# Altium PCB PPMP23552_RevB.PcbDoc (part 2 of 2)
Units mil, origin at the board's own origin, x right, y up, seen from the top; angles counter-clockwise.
Board outline 4950 x 3450 mil, 4 copper layers (Top Layer 1, Layer 2, Layer 3, Bottom Layer), stack 75.824 mil thick; 113 components, 58 nets, 311 pads, 148 vias.
Unrouted connection lines stored in the file: 10.
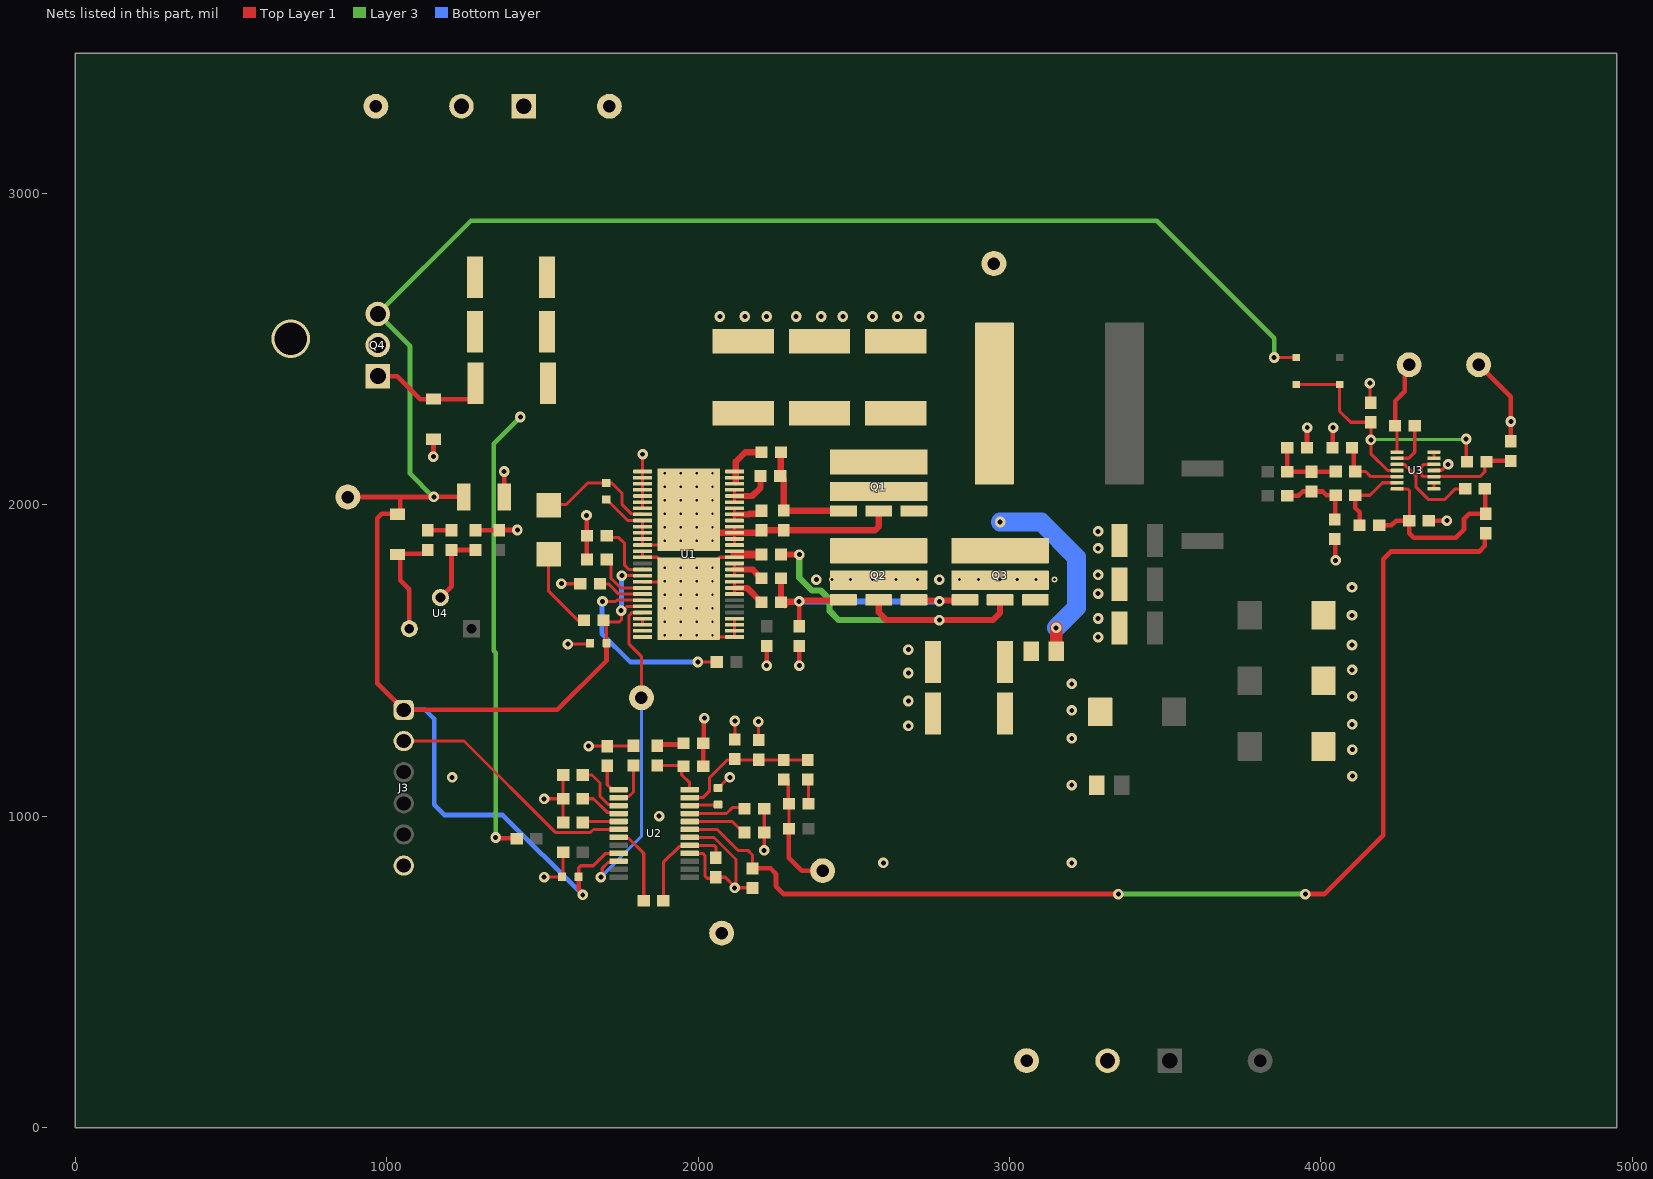
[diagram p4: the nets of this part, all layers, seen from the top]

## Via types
v1: diameter 34, hole 16, Top Layer 1 to Bottom Layer, 89 vias
v2: diameter 19.68, hole 7.87, Top Layer 1 to Bottom Layer, tented both sides, 48 vias
v3: diameter 20, hole 10, Top Layer 1 to Bottom Layer, 11 vias

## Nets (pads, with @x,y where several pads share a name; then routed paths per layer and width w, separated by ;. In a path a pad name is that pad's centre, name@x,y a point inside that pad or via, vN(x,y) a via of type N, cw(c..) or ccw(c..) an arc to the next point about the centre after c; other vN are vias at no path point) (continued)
GND: C3.1 C4.2 C5.2 C6.2 C7.2 C8.1 C10.2 C11.1 C12.1 C13.1 C14.1 C15.1 C16.2 C17.2 C18.2 C19.1 C20.2 C21.1 C22.2 C24.1 C25.1 C26.1 C27.2 C29.2 C30.2 C31.2 D5.2 H1.1 J1.2 J2.2 J3.6 Q2.4 Q3.4 R8.2 R11.1 R12.1 R13.1 R16.1 R18.1 R19.2 R20.2 R21.1 R22.1 R23.2 R25.1 R27.2 R28.2 R29.1 R30.2 R32.1 R46.1 R47.1 TP3.1 TP7.1 TP8.1 TP11.1 U1.1 U1.2 U1.3 U1.4 U1.5 U1.6 U1.7 U1.14 U1.15 U1.19 U1.25 U1.26 U1.27 U1.28 U1.29 U1.30 U1.31 U1.32 U1.42 U1.43 U1.58 U2.16 U2.18 U3.11 | length 3843.7
  Top Layer 1 w10: C30.2@1361.57,1918.22 C30.2@1362.68,1919.33 ; v1(1505.57,804.31) 1566.59,804.31 R18.1@1566.59,884.48 ; v1(1505.57,1056.05) R19.2@1566.59,1056.05 ; v1(1560.92,1746.72) R13.1@1620.17,1746.72 ; C20.2@1566.59,979.61 R23.2@1566.59,1132.48 ; v1(1582.03,1552.78) C3.1@1642.89,1552.78 ; R13.1@1618.69,1746.72 R13.1@1624.58,1752.61 ; v1(1648.44,1225) R21.1@1713.31,1225 ; R20.2@1786.17,1225 1716.05,1225 1791.57,1225 R20.2@1792.56,1225.99 ; U1.26@1821.85,1614.97 U1.25@1821.85,1634.66 ; U1.19@1821.85,1752.77 1890.75,1752.77 v2(1892.72,1754.74) ; U1.14@1821.85,1851.19 U1.15@1821.85,1831.51 1869.1,1831.51 U1.58@1969.49,1731.12 ; U1.7@1821.85,1988.99 U1.6@1821.85,2008.68 U1.5@1821.85,2028.36 U1.4@1821.85,2048.05 U1.3@1821.85,2067.73 U1.2@1821.85,2087.42 U1.1@1821.85,2107.1 v1(1821.85,2162.45) ; U1.58@1969.49,1698.64 U1.58@1969.49,1731.12 ; U2.16@1972.92,880.68 2014.75,880.68 2021.65,873.78 2021.65,807.84 2028.55,800.94 2054.14,800.94 C10.2@2057.09,803.89 2087.44,803.89 2117.13,774.2 v1(2117.13,770.2) ; U2.18@1972.92,931.86 2050.92,931.86 2121.89,860.9 2121.89,792.2 2121.72,792.04 2121.72,774.8 v1(2117.13,770.2) ; v2(2046.26,1581.51) 2052.17,1575.6 U1.29@2117.13,1575.6 U1.30@2117.13,1595.29 U1.31@2117.13,1614.97 U1.32@2117.13,1634.66 ; C24.1@2063.88,1090.53 2064.86,1090.53 2099.04,1124.7 v1(2101.78,1124.7) ; 2117.13,1840.95 U1.42@2117.13,1831.51 2069.89,1831.51 U1.58@1969.49,1731.12 ; v1(2118.19,1305.66) 2118.19,1246.72 R11.1@2118.25,1246.66 ; R22.1@2174.88,769.44 2174.12,770.2 v1(2117.13,770.2) ; v1(2193.58,1303.69) 2193.58,1245.8 R12.1@2194.69,1244.69 ; v1(2212.33,890.37) C22.2@2212.33,947.88 R25.1@2212.33,1024.38 ; v1(4157.64,2391) 4157.64,2331.32 C25.1@4160.78,2328.18 ; U3.11@4363.11,2110.32 4364.02,2111.22 4387.97,2111.22 4406.75,2130 v1(4408.65,2130)
  Top Layer 1 w15: v1(1150,2155) D5.2@1150,2210.53 ; R46.1@1285.07,1918.22 C30.2@1361.57,1918.22 ; C30.2@1362.68,1919.33 v1(1419.63,1919.33) ; C29.2@1377.29,2025 v1(1377.29,2107.21) ; v1(1641.62,1966.15) 1642.6,1965.16 1642.6,1901.77 C4.2@1643.58,1900.78 ; C4.2@1641.96,1894.64 1642.42,1894.18 1642.42,1823.76 R16.1@1642.89,1823.3 ; C19.1@2016.5,1160.79 C11.1@2016.5,1234.85 2018.25,1236.6 2018.25,1313.25 v1(2020,1315) ; v1(2220,1483.38) C21.1@2220,1546.88 ; v1(2325,1483.38) R29.1@2325,1546.88 ; C31.2@3955.27,2183.52 3955.8,2184.05 3955.8,2247.35 v1(3956.33,2247.87) ; R47.1@4037.05,2183.52 4038.15,2184.63 4038.15,2246.77 v1(4039.25,2247.87) ; C26.1@4045.15,1890 4046.4,1888.75 4046.4,1823.26 v1(4047.66,1822.01) ; C27.2@4346.5,1949.37 v1(4405,1949.37) ; TP11.1@4506.75,2450 4610,2346.75 v1(4610,2267.62) R32.1@4610,2204.11
  Top Layer 1 w25: 2117.13,1840.95 2203.1,1840.95 R30.2@2203.58,1840.47
  other v1: 2595,850 3200,850 1875,1000 3200,1100 1210,1125 4101.02,1128.54 4101.02,1213.54 3200,1250 2675,1290 4100.81,1295 3200,1340 2675,1370 4100.81,1385 3200,1425 2675,1460 4100.81,1470 2675,1535 4100,1550 3285,1575 3285,1635 4100,1645 3285,1715 4100,1735 2380,1760 2775,1760 3285,1775 3285,1860 3285,1915 2070,2605 2150,2605 2220,2605 2315,2605 2395,2605 2465,2605 2560,2605 2640,2605 2710,2605
  other v2: 1892.72,1581.51 1943.9,1581.51 1995.08,1581.51 1892.72,1624.82 1943.9,1624.82 1995.08,1624.82 2046.26,1624.82 1892.72,1668.12 1943.9,1668.12 1995.08,1668.12 2046.26,1668.12 1892.72,1711.43 1943.9,1711.43 1995.08,1711.43 2046.26,1711.43 1943.9,1754.74 1995.08,1754.74 2046.26,1754.74 1892.72,1798.05 1943.9,1798.05 1995.08,1798.05 2046.26,1798.05
  other v3: 2430,1760 2490,1760 2560,1760 2635,1760 2705,1760 2840,1760 2900,1760 2970,1760 3025,1760 3085,1760 3145,1760
LSG: Q2.1 Q2.2 Q3.1 Q3.2 R24.2 R26.2 R29.2 | length 984.1
  Top Layer 1 w15: R24.2@2278.34,1674.33 2291.15,1687.14 ; R29.2@2325,1609.87 v1@2325,1674.33
  Top Layer 1 w20: R24.2@2266.57,1688.76 R24.2@2278.28,1688.76 ; R26.2@2266.57,1763.96 2266.57,1700.48 2272.43,1694.62 R24.2@2278.28,1688.76 ; Q2.1@2467.01,1695 2464.39,1692.38 2327.39,1692.38 2323.77,1688.76 R24.2@2278.28,1688.76 ; Q2.2@2692.99,1695 2695.49,1692.5 2772.5,1692.5 v1(2775,1690) 2777.5,1692.5 2854.51,1692.5 Q3.1@2857.01,1695
  Bottom Layer w20: v1(2324.77,1689.76) 2324.89,1689.88 2774.88,1689.88 v1(2775,1690)
NetC1_1: C1.1 D1.1 U1.8 | length 393.1
  Top Layer 1 w10: D1.1@1520.02,2001.23 1576.59,2001.23 1645.47,2070.11 C1.1@1705.39,2070.11 1723.1,2070.11 1755.13,2038.09 1755.13,2002.23 1787.15,1970.21 1820.95,1970.21 U1.8@1821.85,1969.3
NetC2_2: C2.2 U1.48 U1.49 U1.50 | length 131.3
  Top Layer 1 w10: U1.48@2117.13,1949.62 U1.49@2117.13,1969.3 U1.50@2117.13,1988.99
  Top Layer 1 w20: U1.49@2117.13,1969.3 2162.61,1969.3 2164.74,1971.43 2194.87,1971.43 2203.58,1980.13 C2.2@2203.58,1981.12
NetC4_1: C4.1 U1.17 | length 201.6
  Top Layer 1 w10: C4.1@1704.95,1894.64 1745.31,1894.64 1764.01,1875.94 1764.01,1805.94 1777.82,1792.14 U1.17@1821.85,1792.14 U1.17@1820.95,1793.05
NetC9_1: C9.1 R4.1 | length 82.4
  Top Layer 1 w10: R4.1@2354.65,1040.06 2354.65,1106.28 C9.1@2366.09,1117.72
NetC9_2: C9.2 R5.1 R11.2 R12.2 U2.23 | length 468.8
  Top Layer 1 w10: U2.23@1972.92,1059.82 2015.45,1059.82 2037.22,1081.59 2037.22,1124.27 2092.68,1179.73 2092.68,1180.71 2120.85,1180.71 2169.36,1180.71 2194.69,1180.71 2289.59,1180.71 C9.2@2366.09,1180.71
NetC10_1: C10.1 R17.2 U2.17 | length 350.4
  Top Layer 1 w10: R17.2@1888.43,728.53 1888.43,851.65 1939.2,902.41 1969.06,902.41 U2.17@1972.92,906.27 2051.24,906.27 2057.09,900.42 C10.1@2057.09,866.88
NetC11_2: C11.2 R15.2 | length 87.8
  Top Layer 1 w15: R15.2@1869.33,1225.99 1873.76,1230.42 1949.07,1230.42 C11.2@1953.5,1234.85
NetC19_2: C19.2 R15.1 U2.24 | length 165.1
  Top Layer 1 w10: R15.1@1869.33,1163 1945.45,1163 1947.66,1160.79 1947.66,1132.58 1972.92,1107.32 U2.24@1972.92,1085.41
NetC20_1: C20.1 U2.5 | length 116.4
  Top Layer 1 w10: C20.1@1629.58,979.61 1633.02,983.04 U2.5@1744.57,983.04
NetC22_1: C22.1 U2.20 | length 188
  Top Layer 1 w10: U2.20@1972.92,983.04 2110.24,983.04 2145.4,947.88 C22.1@2146.39,947.88
NetC23_1: C23.1 R27.1 R28.1
NetC24_2: C24.2 U2.22 | length 92.3
  Top Layer 1 w10: U2.22@1972.92,1034.23 1974.5,1035.8 2062.3,1035.8 C24.2@2063.88,1037.38
NetC25_2: C25.2 D2.1 D3.1 R31.1 U3.4 | length 923.1
  Top Layer 1 w10: D2.1@3920.76,2386.7 D3.1@4060.15,2386.7 4060.15,2301.06 4096.02,2265.18 C25.2@4160.78,2265.18 v1(4160.78,2208.82) 4160.78,2164.62 4215.08,2110.32 U3.4@4245,2110.32 ; v1(4466.85,2211.31) 4466.85,2141.12 R31.1@4469.35,2138.62
  Layer 3 w10: v1(4160.78,2208.82) 4162.4,2210.44 4459.38,2210.44 v1@4461,2212.07
NetC26_2: C26.2 C28.1 R38.2 R39.1 | length 244.7
  Top Layer 1 w15: R38.2@3892.28,2029.43 3928.01,2029.43 3941.46,2042.87 C28.1@3970,2042.87 4005.9,2042.87 4018.13,2030.65 R39.1@4047.66,2030.65 4046.4,2029.4 4046.4,1954.24 C26.2@4045.15,1952.99
NetC27_1: C27.1 R36.2 R37.1 R40.2 U3.7 | length 665.9
  Top Layer 1 w10: U3.7@4245,2051.26 4278.11,2051.26 4285,2044.37 4285,1950.87 C27.1@4283.5,1949.37
  Top Layer 1 w15: R40.2@4187.5,1934.38 4226.78,1934.38 4241.77,1949.37 C27.1@4283.5,1949.37 4283.5,1909.37 4298.5,1894.37 4433.46,1894.37 4460,1920.91 4460,1955.39 4476.3,1971.69 R36.2@4529.45,1971.69 4527.97,1973.17 4527.97,2049.78 R37.1@4526.5,2051.26
NetC28_2: C28.2 C31.1 R43.2 R44.1 | length 233.5
  Top Layer 1 w15: C31.1@3892.28,2183.52 R43.2@3892.28,2105.87 C28.2@3970,2105.87 3970.61,2106.48 4047.05,2106.48 R44.1@4047.66,2107.09
NetD1_2: D1.2 R1.2 | length 282.7
  Top Layer 1 w10: D1.2@1520.02,1843.75 1520.02,1722.56 1613.36,1629.22 R1.2@1642.89,1629.22
NetD4_2: D4.2 R41.2 U4.3 | length 354.3
  Top Layer 1 w10: R41.2@1118.91,1842.65 R41.2@1131.48,1855.22
  Top Layer 1 w15: U4.3@1072.47,1602.15 1072.47,1728.59 1043.42,1757.64 1043.42,1842.46 R41.2@1127.56,1842.46
NetD5_1: D5.1 Q4.1 R33.2 | length 384.1
  Top Layer 1 w15: Q4.1@971.41,2413.19 1033.77,2413.19 1107.5,2339.47 D5.1@1150,2339.47 1266.91,2339.47 1285,2357.56 R33.2@1285,2390
NetQ1_1: Q1.1 Q1.2 R3.2 R6.2 R9.2 | length 390.8
  Top Layer 1 w20: R6.2@2269.52,2171.93 R6.2@2266.57,2168.98 2265.09,2167.5 2265.09,2094.02 R3.2@2263.61,2092.54 2264.6,2092.54 2273.3,2083.84 2273.3,2082.86 2275,2081.16 R9.2@2275,1981.5 2275.75,1980.75 2466.26,1980.75 Q1.1@2467.01,1980
NetQ4_2: Q4.2 R34.1 R35.1
NetR2_1: R2.1 R4.2 R5.2 TP2.1 | length 377.4
  Top Layer 1 w10: R5.2@2289.59,1117.72 2289.59,1042.13 R4.2@2291.66,1040.06 R2.1@2291.66,960.05
  Top Layer 1 w15: R2.1@2291.66,960.05 2291.66,866.88 2333.54,825 TP2.1@2400,825
NetR3_1: R3.1 U1.51 U1.52 U1.53 | length 171.2
  Top Layer 1 w10: U1.51@2117.13,2008.68 U1.52@2117.13,2028.36 U1.53@2117.13,2048.05
  Top Layer 1 w20: U1.52@2117.13,2028.36 2173.65,2028.36 2200.62,2055.34 R3.1@2200.62,2092.54
NetR6_1: R6.1 U1.54 U1.55 U1.56 | length 161.3
  Top Layer 1 w20: U1.54@2121.23,2072.4 2121.23,2138.82 2151.38,2168.98 R6.1@2203.58,2168.98
NetR7_1: R7.1 U1.22 | length 641.7
  Top Layer 1 w10: v1(1693.08,1689.76) 1735.01,1689.76 1739.44,1694.19 1821.38,1694.19 U1.22@1821.85,1693.71 ; v1(1999.01,1495.3) R7.1@2060.04,1495.3
  Bottom Layer w10: v1@1691.2,1687.87 v1(1693.08,1689.76)
  Bottom Layer w15: v1@1691.2,1687.87 1691.2,1586.16 1782.06,1495.3 v1(1999.01,1495.3)
NetR13_2: R13.2 U1.21 | length 150.8
  Top Layer 1 w10: R13.2@1684.92,1746.93 1686.64,1745.21 1713.75,1745.21 1745.56,1713.4 U1.21@1821.85,1713.4
NetR16_2: R16.2 U1.20 | length 176.4
  Top Layer 1 w10: R16.2@1719.37,1825.57 1720.56,1824.37 1720.56,1763.67 1751.15,1733.08 U1.20@1821.85,1733.08
NetR17_1: R17.1 U2.7 | length 254.3
  Top Layer 1 w10: U2.7@1744.57,931.86 1748.43,928.01 1778.29,928.01 1825.44,880.86 R17.1@1825.44,728.53
NetR19_1: R19.1 U2.4 | length 134.6
  Top Layer 1 w10: R19.1@1629.58,1056.05 1664.27,1056.05 1707.82,1012.49 1740.71,1012.49 U2.4@1744.57,1008.64
NetR20_1: R20.1 U2.2 | length 140.6
  Top Layer 1 w10: U2.2@1744.57,1059.82 1748.43,1063.67 1778.29,1063.67 1792.56,1077.94 R20.1@1792.56,1163
NetR21_2: R21.2 U2.1 | length 103.8
  Top Layer 1 w10: R21.2@1708.14,1162.01 1708.14,1101.17 1723.9,1085.41 U2.1@1744.57,1085.41
NetR22_2: R22.2 R36.1 U2.19 | length 3712.2
  Top Layer 1 w10: U2.19@1972.92,957.45 2061.21,957.45 2128.29,890.37 2159.84,890.37 2174.88,875.33 R22.2@2174.88,832.43
  Top Layer 1 w15: R22.2@2174.88,832.43 2232.57,832.43 2250,815 2250,775 2275,750 v1(3350,750) ; v1(3950,750) 4011.23,750 4200,938.77 4200,1825 4225,1850 4508.49,1850 4526.5,1868.01 4526.5,1905.75 R36.1@4529.45,1908.7
  Layer 3 w15: v1(3350,750) v1(3950,750)
NetR23_1: R23.1 U2.3 | length 180.7
  Top Layer 1 w10: R23.1@1629.58,1132.48 1659.11,1132.48 1684.98,1106.61 1684.98,1063.96 1710.85,1038.08 1740.71,1038.08 U2.3@1744.57,1034.23
NetR24_1: R24.1 U1.36 U1.37 U1.38 | length 144.7
  Top Layer 1 w10: U1.36@2117.13,1713.4 U1.37@2117.13,1733.08 U1.38@2117.13,1752.77
  Top Layer 1 w20: U1.37@2117.13,1733.08 2157.03,1733.08 2202.59,1687.53 R24.1@2203.58,1687.53
NetR25_2: R25.2 U2.21 | length 185.5
  Top Layer 1 w10: U2.21@1972.92,1008.64 2091.37,1008.64 2110.24,1027.5 2146.22,1027.5 R25.2@2149.34,1024.38
NetR26_1: R26.1 U1.39 U1.40 U1.41 | length 150.1
  Top Layer 1 w10: U1.39@2117.13,1772.45 U1.40@2117.13,1792.14 U1.41@2117.13,1811.82 ; R26.1@2195.08,1772.45 R26.1@2203.57,1763.96
  Top Layer 1 w20: U1.40@2117.13,1792.14 2175.4,1792.14 2187.12,1780.42 2187.12,1779.44 2194.59,1771.96 2202.59,1763.96 R26.1@2203.57,1763.96
NetR31_2: R31.2 R32.2 U3.10 U3.12 | length 389.7
  Top Layer 1 w10: U3.12@4363.11,2130 4331.02,2130 4322.97,2121.95 4322.97,2096.49 4328.83,2090.63 U3.10@4363.11,2090.63 4511.26,2090.63 4526.5,2105.87 R31.2@4526.5,2139.37
  Top Layer 1 w15: R31.2@4526.5,2139.37 4528.25,2141.12 4598.25,2141.12 R32.2@4600,2142.87
NetR37_2: R37.2 U3.3 | length 300.7
  Top Layer 1 w10: U3.3@4245,2130 4245.91,2129.09 4269.86,2129.09 4305.1,2093.86 4305.1,2058.08 4346.5,2016.68 4397.31,2016.68 4431.89,2051.26 R37.2@4463.5,2051.26
NetR39_2: R39.2 R40.1 U3.6 | length 254
  Top Layer 1 w10: R39.2@4110.65,2030.65 4157.64,2030.65 4197.93,2070.94 U3.6@4245,2070.94
  Top Layer 1 w15: R39.2@4110.65,2030.65 4110.65,1989.82 4124.51,1975.97 R40.1@4124.51,1934.38 ; R40.1@4127.95,1934.38 R40.1@4128.93,1934.38
NetR41_1: R41.1 R42.1 | length 76.4
  Top Layer 1 w15: R41.1@1131.48,1918.22 R42.1@1207.92,1918.22
NetR42_2: R42.2 R46.2 U4.2 | length 245.6
  Top Layer 1 w15: U4.2@1172.47,1702.15 1207.92,1737.6 R42.2@1207.92,1855.22 1283.35,1855.22 R46.2@1285.07,1853.5
NetR44_2: R44.2 R47.2 U3.5 | length 222
  Top Layer 1 w10: R44.2@4110.65,2107.09 4144,2107.09 4160.45,2090.63 U3.5@4245,2090.63
  Top Layer 1 w15: R47.2@4100.04,2183.52 4105.34,2178.22 4105.34,2112.39 R44.2@4110.65,2107.09
NetR45_1: R45.1 TP10.1 U3.1 | length 296.3
  Top Layer 1 w10: R45.1@4238.5,2254.37 4245,2247.87 U3.1@4245,2169.37
  Top Layer 1 w15: R45.1@4238.5,2254.37 4238.5,2333.51 4269.23,2364.24 4269.23,2449.37 TP10.1@4269.86,2450
NetR45_2: R45.2 U3.2 | length 149.6
  Top Layer 1 w10: U3.2@4245,2149.69 4281.81,2149.69 4301.5,2169.37 R45.2@4301.5,2254.37
NetU3_8: U3.8 U3.9 | length 19.7
  Top Layer 1 w10: U3.8@4363.11,2051.26 U3.9@4363.11,2070.94
NetU3_13: U3.13 U3.14 | length 19.7
  Top Layer 1 w10: U3.13@4363.11,2149.69 U3.14@4363.11,2169.37
PWM: TP4.1 U1.24 U2.10 | length 1050.1
  Top Layer 1 w10: v1(1687.51,804.31) 1692.1,808.9 1692.1,832.48 1710.85,851.23 1740.71,851.23 U2.10@1744.57,855.09 ; TP4.1@1817.92,1380.4 1817.92,1513.3 1778.47,1552.74 1778.47,1644.76 1787.15,1653.44 1820.95,1653.44 U1.24@1821.85,1654.34
  Bottom Layer w10: v1(1687.51,804.31) 1817.92,934.72 TP4.1@1817.92,1380.4
SS: Q2.5 Q3.5 R30.1 | length 1152.5
  Top Layer 1 w20: R30.1@2266.57,1840.47 2266.8,1840.23 2324.77,1840.23 v1(2325,1840) ; Q2.5@2580,1695 2580,1655.08 2605.08,1630 v1(2775,1630) 2946.68,1630 2970,1653.32 Q3.5@2970,1695
  Layer 3 w20: v1(2325,1840) 2325,1765.68 2365.55,1725.13 2393.04,1725.13 2422.11,1696.06 2422.11,1659.07 2451.17,1630 v1(2775,1630)
SW: C1.2 C2.1 C23.2 L1.1 Q1.4 Q1.5 Q2.3 Q3.3 R9.1 TP5.1 U1.9 U1.10 U1.11 U1.12 U1.13 U1.44 U1.45 U1.46 U1.47 U1.57 | length 1885.6
  Top Layer 1 w10: C1.2@1705.39,2016.96 1706.37,2016.96 1773.71,1949.62 U1.9@1821.85,1949.62 U1.10@1821.85,1929.93 U1.11@1821.85,1910.25 U1.12@1821.85,1890.56 U1.13@1821.85,1870.88 1874.1,1870.88 1969.49,1966.27 U1.57@1969.49,1984.07 ; U1.57@2001.44,1934.32 U1.57@2048.69,1887.08 ; v2(2046.26,1884.66) U1.57@2052.17,1890.56 ; U1.44@2117.13,1870.88 U1.45@2117.13,1890.56 U1.46@2117.13,1910.25 U1.47@2117.13,1929.93
  Top Layer 1 w20: U1.57@1969.49,1984.07 2043.31,1910.25 U1.46@2117.13,1910.25 2195.7,1910.25 C2.1@2203.58,1918.12 2203.77,1918.31 2274.81,1918.31 R9.1@2275,1918.5 2568.28,1918.5 2580,1930.22 Q1.5@2580,1980
  Top Layer 1 w40: Q3.3@2970,1852.5 Q3.3@2972.5,1855 ; C23.2@3150,1530 v1(3150,1605)
  Bottom Layer w60: v1(2970,1945) 3101.85,1945 3215,1831.85 3215,1670 v1(3150,1605)
  other v2: 1892.72,1884.66 1943.9,1884.66 1995.08,1884.66 1892.72,1927.97 1943.9,1927.97 1995.08,1927.97 2046.26,1927.97 1892.72,1971.27 1943.9,1971.27 1995.08,1971.27 2046.26,1971.27 1892.72,2014.58 1943.9,2014.58 1995.08,2014.58 2046.26,2014.58 1892.72,2057.89 1943.9,2057.89 1995.08,2057.89 2046.26,2057.89 1892.72,2101.19 1943.9,2101.19 1995.08,2101.19 2046.26,2101.19
SYNC: J3.2 U2.6 | length 815.2
  Top Layer 1 w10: J3.2@1054.75,1241.4 1248.21,1241.4 1541.57,948.03 1654.6,948.03 1664.02,957.45 U2.6@1744.57,957.45
Vbias: C3.2 C8.2 C29.1 D2.2 D4.1 J3.1 Q4.3 R1.1 TP9.1 U1.18 U1.23 U2.9 | length 7524.5
  Top Layer 1 w10: C8.2@1616.57,805 1616.57,834.73 1622.63,840.78 1663.62,840.78 1703.52,880.68 U2.9@1744.57,880.68 ; C3.2@1705.88,1552.78 1705.88,1629.22 1710.87,1624.23 1747.65,1624.23 1753.51,1630.08 1753.51,1659.65 v1(1752.92,1660.24) ; v1@1753.51,1661.22 1753.6,1661.31 1760.09,1661.31 1772.82,1674.03 U1.23@1821.85,1674.03 ; v1(1755.13,1772.45) U1.18@1821.85,1772.45 ; v1(3850,2473.31) D2.2@3920.76,2473.31
  Top Layer 1 w15: TP9.1@875,2025 1043.42,2025 ; D4.1@1034.75,1971.4 984.75,1971.4 969.75,1956.4 969.75,1426.4 J3.1@1054.75,1341.4 1547.98,1341.4 1705.88,1499.29 C3.2@1705.88,1552.78 ; D4.1@1034.75,1978.53 1043.42,1969.86 1043.42,2025 ; v1@1150,2025 1043.42,2025 ; v1(1151.39,2025.77) 1246.6,2025.77 C29.1@1247.37,2025 ; C8.2@1616.57,805 1616.57,765.38 1629.58,752.37 v1(1629.58,747.23)
  Layer 3 w15: v1@1150,2025 1075,2100 1075,2509.6 Q4.3@971.41,2613.19 1270.71,2912.5 3472.5,2912.5 3850,2535 v1(3850,2473.31)
  Bottom Layer w10: v1(1752.92,1660.24) v1@1754.02,1661.34 ; v1@1754.02,1771.35 v1(1755.13,1772.45) v1@1759.72,1767.86
  Bottom Layer w15: J3.1@1054.75,1341.4 1123,1341.4 1152.19,1312.21 1152.19,1037.34 1185.78,1003.75 1373.06,1003.75 v1(1629.58,747.23) ; v1@1754.02,1661.34 v1@1754.02,1771.35
Vin: C5.1 C6.1 C7.1 J1.1 Q1.3 R10.2 R33.1 R34.2 R35.2 TP1.1 | length 1457.3
  Top Layer 1 w15: v1(1350,931.51) 1351.75,929.76 1415.56,929.76 R10.2@1417.31,928.01
  Layer 3 w15: v1(1350,931.51) 1350,1525.01 1343.53,1531.48 1343.53,2196.5 v1(1429,2281.98)
pads on no net: H2.0 H3.0 H4.0 H5.0 J3.3 J3.4 U1.16 U2.11 U2.12 U2.13 U2.14 U2.15

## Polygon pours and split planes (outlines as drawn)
GND on Top Layer 1 "TOP_LAYER_1_GND_P026" (solid, remove dead copper, pour order 26): 50,3400 50,50 4900,50 4900,3400
NetC23_1 on Top Layer 1 "TOP_LAYER_1_NETC23_1_P025" (solid, remove dead copper, pour order 25): 3095,1570 2925,1570 2925,1250 3095,1250
NetQ4_2 on Top Layer 1 "TOP_LAYER_1_NETQ4_2_P024" (solid, remove dead copper, pour order 24): 1350,2475 900,2475 900,2550 1150,2550 1150,2850 1350,2850
NetD5_1 on Top Layer 1 "TOP_LAYER_1_NETD5_1_P022" (solid, remove dead copper, pour order 22): 900,2300 1350,2300 1350,2450 900,2450
CS- on Top Layer 1 "TOP_LAYER_1_CS-_P021" (solid, remove dead copper, pour order 21): 3865,1950 3865,50 3435,50 3435,1950
CS+ on Top Layer 1 "TOP_LAYER_1_CS+_P020" (solid, remove dead copper, pour order 20): 3200,2000 3465,2000 3700,2000 3700,2850 3200,2850
SW on Top Layer 1 "TOP_LAYER_1_SW_P019" (solid, remove dead copper, pour order 19): 2400,2070 2400,2015 2540,2015 2540,1930 2400,1930 2400,1815 3135,1815 3135,2850 2825,2850 2825,1930 2620,1930 2620,2015 2750,2015 2750,2070
Vin on Top Layer 1 "TOP_LAYER_1_VIN_P017" (solid, remove dead copper, pour order 17): 1400,3400 1400,2850 1400,2250 2400,2250 2400,2100 2800,2100 2800,2425 1950,2425 1950,3400
GND on Bottom Layer "BOTTOM_LAYER_GND_P023" (solid, pour order 23): 50,3400 50,50 4900,50 4900,3400
CS- on Bottom Layer "BOTTOM_LAYER_CS-_P018" (solid, remove dead copper, pour order 18): 3865,1950 3865,50 3435,50 3435,1950
SW on Bottom Layer "BOTTOM_LAYER_SW_P011" (solid, remove dead copper, pour order 11): 2072.1,2150.72 2072.1,1852.1 2070,1850 1870,1850 1870,2150
GND on Layer 2 "LAYER_2_GND_P014" (solid, pour order 14): 50,3400 50,50 4900,50 4900,3400
GND on Layer 3 "LAYER_3_GND_P015" (solid, pour order 15): 50,3400 50,50 4900,50 4900,3400

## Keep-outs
Keep-Out Layer:
  text ".Layer_Name" at 577,-858.49 h60

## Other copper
Top Layer 1:
  rectangle net GND: 3070,1730 3200,1785
  rectangle net GND: 2690,1730 2860,1785
  rectangle net GND: 2360,1730 2455,1785
  rectangle net SW: 2725,2015 2895,2070
  text ".Layer_Name" at 577,-858.49 h60
Bottom Layer:
  text ".Layer_Name" at 577,-858.49 h60

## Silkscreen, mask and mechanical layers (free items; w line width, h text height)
Top Overlay:
  text "VIN" at 1858,3253 h50
  text "GND" at 683,3248 h50
  text "'.PRJ_Number'.PCB_Rev" at 1175,262.76 h108.27
  text "GND" at 2955.92,48 h50
  text "VOUT" at 3777.5,48 h50
  text ".Layer_Name" at 577,-858.49 h60
Bottom Overlay:
  text ".Layer_Name" at 577,-858.49 h60
Top Paste:
  text ".Layer_Name" at 577,-858.49 h60
Bottom Paste:
  text ".Layer_Name" at 577,-858.49 h60
Top Solder:
  text ".Layer_Name" at 577,-858.49 h60
  text ".Layer_Name" at 577,-858.49 h60
Bottom Solder:
  text ".Layer_Name" at 577,-858.49 h60
Drill Guide:
  text ".Layer_Name" at 577,-858.49 h60
M1 Board Outline:
  the board outline again, w10
  text ".Layer_Name" at 577,-858.49 h60
M2 Board Dimensions:
  rectangle: 0,-275 125,-150
  rectangle: 125,-400 500,-275
  lines w7: 0,-275 1000,-275 ; 125,-400 125,-150 ; 250,-400 250,-150 ; 500,-400 500,-150 ; 750,-400 750,-150 ; 0,-400 1000,-400 1000,-150 0,-150 0,-400
  text ".Layer_Name" at 577,-858.49 h60
M3 3D STEP Top:
  text ".Layer_Name" at 577,-858.49 h60
M4 3D STEP Bottom:
  text ".Layer_Name" at 577,-858.49 h60
M5 Assembly Top:
  lines w10: -292,-930.17 6308,-930.17 ; -292,-726.83 6310,-726.83 ; -292,-523.5 -292,-1133.5 3713,-1133.5 6310,-1133.5 6310,-523.5 -291.5,-523.5 -291.5,-1133.5 1284,-1133.5 ; 2173,-1133.5 2173,-523.5 ; 3440,-726.83 3440,-523.5 ; 4280,-726.83 4280,-523.5 ; 4902,-1140 4902,-937.17
  text "COMPONENTS MARKED 'DNP' SHOULD NOT BE POPULATED." at 1153.5,-318.5 h60
  text "ASSEMBLY VARIANT:" at 1153,-434 h60
  text ".VariantName" at 2189,-434 h60
  text "PCB VIEWED FROM TOP SIDE" at -228.5,-655.67 h60
  text "BOARD #:" at 2248,-655.67 h60
  text ".PRJ_Number" at 2793.5,-655.67 h60
  text "REV:" at 3638,-655.67 h60
  text ".PCB_Rev" at 3929.5,-655.67 h60
  text "SVN REV:" at 4476,-655.67 h60
  text ".VersionControl_RevNumber" at 4982,-655.67 h60
  text "TID #:" at 2248,-859 h60
  text ".TID" at 2793.5,-859 h60
  text "PLOT NAME =" at -228.5,-1064.34 h60
  text ".plot_File_Name" at 577,-1064.34 h60
  text "GENERATED    :" at 2250,-1064.34 h60
  text ".Print_Date" at 3119.5,-1064.34 h60
  text ".Print_Time" at 3848.5,-1064.34 h60
  text "TEXAS INSTRUMENTS" at 5113,-1064.34 h60
M6 Assembly Bottom:
  lines w10: -292.5,-727.33 6309.5,-727.33 ; -290.5,-930.67 6309.5,-930.67 ; 1115.5,-1140.5 1115.5,-937.67 ; 1737.5,-727.33 1737.5,-524 ; 2577.5,-727.33 2577.5,-524 ; 3844.5,-1134 3844.5,-524 ; 4733.5,-1134 6309,-1134 6309,-524 -292.5,-524 -292.5,-1134 2304.5,-1134 6309.5,-1134 6309.5,-524
  text "COMPONENTS MARKED 'DNP' SHOULD NOT BE POPULATED." at 6102,-318 h60
  text ".VariantName" at 5058,-434 h60
  text "ASSEMBLY VARIANT:" at 6097,-434 h60
  text ".VersionControl_RevNumber" at 1035.5,-656.17 h60
  text "SVN REV:" at 1541.5,-656.17 h60
  text ".PCB_Rev" at 2088,-656.17 h60
  text "REV:" at 2379.5,-656.17 h60
  text ".PRJ_Number" at 3224,-656.17 h60
  text "BOARD #:" at 3769.5,-656.17 h60
  text "PCB VIEWED FROM BOTTOM SIDE" at 6246,-656.17 h60
  text ".TID" at 3224,-859.5 h60
  text "TID #:" at 3769.5,-859.5 h60
  text "TEXAS INSTRUMENTS" at 904.5,-1064.84 h60
  text ".Print_Time" at 2169,-1064.84 h60
  text ".Print_Date" at 2898,-1064.84 h60
  text "GENERATED    :" at 3767.5,-1064.84 h60
  text ".plot_File_Name" at 5440.5,-1064.84 h60
  text "PLOT NAME =" at 6246,-1064.84 h60
M9 Title Sheet:
  drawing of 57 lines, arcs and shapes, not listed
  text "1" at 739.84,8036.5 h70
  text "2" at 3235.5,8036.5 h70
  text "3" at 5724.84,8036.5 h70
  text "4" at 8231.51,8036.5 h70
  text "5" at 10730.5,8036.5 h70
  text "6" at 13235.5,8036.5 h70
  text "A" at -416.5,6893.5 h70
  text "A" at 14383.5,6893.5 h70
  text "B" at -416.5,4513.5 h70
  text "B" at 14383.5,4513.5 h70
  text "C" at -416.5,2138.5 h70
  text "C" at 14383.5,2138.5 h70
  text "PROJECT TITLE:" at 11343.5,277.5 h45
  text ".PRJ_Title" at 11393.5,144.17 h70
  text "DESIGNED FOR:" at 11343.5,-23.5 h45
  text ".PRJ_Customer" at 11393.5,-163.5 h70
  text "D" at -416.5,-231.5 h70
  text "D" at 14383.5,-231.5 h70
  text "FILE NAME:" at 11343.5,-323.5 h45
  text ".PCB_File_Name_No_Path" at 11393.5,-443.5 h70
  text "Texas Instruments (TI) and/or its licensors do not warrant the accuracy or completeness of this specification" at 6374,-605.34 h45
  text "ENGINEER:" at 11343.5,-613.5 h45
  text "LAYOUT BY:" at 12848.5,-613.5 h45
  text "or any information contained therein. TI and/or its licensors do not warrant that this design will meet" at 6329.01,-718 h45
  text ".PRJ_Engineer" at 11393.5,-768.49 h70
  text ".PCB_Layout" at 12899,-768.49 h70
  text "the specifications, will be suitable for your application or fit for any particular purpose, or will operate in" at 6329.01,-830.67 h45
  text ".Layer_Name" at 577,-858.49 h60
  text "ALTIUM DESIGNER VERSION:" at 12848.5,-923.5 h45
  text "an implementation. TI and/or its licensors do not warrant that the design is production worthy. You should" at 6329.01,-943.33 h45
  text "completely validate and test your design implementation to confirm the system functionality for your application." at 6374,-1056 h45
  text ".print_Scale" at 11393.5,-1056.83 h70
  text ".Application_BuildNumber" at 12899,-1056.83 h70
  text "1" at 739.84,-1263.5 h70
  text "2" at 3235.5,-1263.5 h70
  text "3" at 5724.84,-1263.5 h70
  text "4" at 8231.51,-1263.5 h70
  text "5" at 10730.5,-1263.5 h70
  text "6" at 13235.5,-1263.5 h70
M10 Fab Notes:
  drawing of 189 lines, arcs and shapes, not listed
  text "DESIGN INFORMATION" at 12382.02,6356.17 h60
  text "MIN. TRACK WIDTH:" at 11737.46,6224.05 h60
  text "8" at 12833.7,6224.05 h60
  text "MIL" at 12988.46,6224.05 h60
  text "7.874" at 12667.32,6102.36 h60
  text "MIN. CLEARANCE:" at 11737.46,6099.92 h60
  text "MIL" at 12988.46,6099.92 h60
  text "MIN. VIA PAD SIZE:" at 11737.46,5975.8 h60
  text "24" at 12803.71,5975.8 h60
  text "MIL" at 12988.46,5975.8 h60
  text "0.05mm (2MIL)" at 12432.46,5845.9 h60
  text "MINIMUM ANNULAR RING" at 11408.23,5837.67 h60
  text "EXTERNAL" at 13140.46,5837.67 h60
  text "PER" at 11608.23,5727.55 h60
  text "IPC-D-275 CLASS 2 LEVEL C" at 11828.23,5727.54 h60
  text "MIL, HOLES" at 13316.46,5627.07 h60
  text "+/-" at 12924,5618.48 h60
  text "+/-" at 13778,5618.48 h60
  text "REGISTRATION TOLERANCES:" at 11408.23,5617.42 h60
  text "METAL" at 12608,5617.42 h60
  text "5" at 13184.2,5617.42 h60
  text "3" at 14017.2,5617.42 h60
  text "MIL" at 14133.46,5617.42 h60
  text "HOLE SIZE TOLERANCE (UNLESS OTHERWISE SPECIFIED):" at 11408.23,5519.1 h60
  text "+/-" at 13778,5516.23 h60
  text "3" at 14017.2,5515.17 h60
  text "MIL" at 14133.46,5515.17 h60
  text "MATERIAL:" at 11333.46,5377.52 h60
  text "FR-4 High Tg" at 12319.9,5249 h60
  text "X" at 12175.46,5241.01 h60
  text "FR-4" at 11754.46,5236.49 h60
  text "OTHER" at 13242.46,5236.49 h60
  text "62 MIL (1.6mm) +/-10%" at 12074.56,5093.46 h60
  text "X" at 11954.46,5091.01 h60
  text "THICKNESS:" at 11408.23,5085.24 h60
  text "OTHER" at 13359.46,5085.24 h60
  text "TOLERANCE:" at 11408.23,4946.92 h60
  text "X" at 12256.46,4946.92 h60
  text "ANSI IPC-6012 TYPE 3 CLASS 2" at 12434.48,4946.92 h60
  text "OTHER +/-" at 12434.46,4802.73 h60
  text "BOW & TWIST:" at 11408.23,4657.54 h60
  text "X" at 12256.46,4657.54 h60
  text "ANSI IPC-6012 TYPE 3 CLASS 2" at 12434.48,4657.54 h60
  text "OTHER +/-" at 12434.46,4510.85 h60
  text "DRILLING:" at 11333.46,4380.23 h60
  text "NC_DRILL FILES" at 13094.46,4275.04 h60
  text "REFERENCE:" at 11408.23,4271.1 h60
  text "X" at 12065.46,4271.01 h60
  text "AS SHOWN" at 12243.46,4271.1 h60
  text "X" at 12966.46,4271.1 h60
  text "OTHER" at 13392.46,4128.85 h60
  text "PTH COPPER THICKNESS:" at 11407.91,4125.32 h60
  text "X" at 12547.14,4125.32 h60
  text "20-30 um" at 12675.14,4125.32 h60
  text "BOARD FINISH:" at 11333.46,3977.73 h60
  text "SILKSCREEN:" at 11488.68,3867.6 h60
  text "X" at 12446.46,3867.6 h60
  text "TOP" at 12563.46,3867.6 h60
  text "X" at 12956.46,3867.6 h60
  text "BOTTOM" at 13074.46,3867.6 h60
  text "SILKSCREEN COLOR:" at 11488.68,3712.41 h60
  text "X" at 12445.46,3712.41 h60
  text "WHITE" at 12563.46,3712.41 h60
  text "OTHER" at 13074.46,3712.41 h60
  text "X" at 12576.46,3568.96 h60
  text "GREEN" at 12694.46,3568.96 h60
  text "OTHER" at 13312.46,3568.96 h60
  text "SOLDER RESIST COLOR:" at 11488.68,3562.1 h60
  text "X" at 12576.46,3414.71 h60
  text "MATTE" at 12694.46,3414.71 h60
  text "SEMI-GLOSS" at 13312,3414.07 h60
  text "IMMERSION GOLD (ENIG)" at 12394.46,3241.94 h60
  text "ENEPIG" at 13732,3234.72 h60
  text "SURFACE FINISH:" at 11333.46,3233.72 h60
  text "X" at 12216.46,3233.72 h60
  text "IMM. TIN/SILVER OR EQUIV" at 11663,3096.4 h60
  text "OTHER" at 13094.46,3092.47 h60
  text "ARRAY/PANEL:" at 11333.46,2937.09 h60
  text "CUT AND TRIM PER M1 BOARD OUTLINE" at 12394.46,2928.87 h60
  text "N.C. ROUTE" at 12394.46,2792.9 h60
  text "X" at 13082.46,2792.9 h60
  text "V. SCORE" at 13260.46,2792.9 h60
  text "CERTIFICATION:" at 11333.46,2663.77 h60
  text "MATERIALS AND WORKMANSHIP FOR ALL PCBS" at 12058.46,2663.77 h60
  text "TO MEET OR EXCEED THE REQUIREMENTS OF:" at 12058.46,2569.71 h60
  text "X" at 11695.97,2441.08 h60
  text "ANSI IPC-A-600F CLASS ->" at 11823.96,2441.08 h60
  text "X" at 13471.97,2441.08 h60
  text "2" at 13581.96,2441.08 h60
  text "1" at 13266.96,2439.58 h60
  text "3" at 13935.96,2439.58 h60
  text "X" at 12507.97,2293.39 h60
  text "RoHS" at 12635.96,2293.39 h60
  text "OTHER" at 13280.36,2293.39 h60
  text "PER ORDER" at 13677.42,2293.39 h60
  text "ALL BOARDS MUST MEET OR EXCEED UL94-V0 REQUIREMENTS." at 11361,2139.57 h60
  text "PCB MUST BEAR THE UL94V-0 UL REGISTERED MATERIAL ID NUMBER" at 11361,2023.5 h60
  text "ADDITIONAL REQUIREMENTS:" at 11333.46,1854.08 h60
  text "MICROSECTION:" at 11408.23,1746.95 h60
  text "YES" at 12313.96,1746.95 h60
  text "REQUIRED" at 13175.46,1602.62 h60
  text "BARE BOARD ELEC. TEST:" at 11408.23,1599.76 h60
  text "NONE" at 12713.96,1599.76 h60
  text "X" at 13057.46,1599.76 h60
  text "PER ORDER" at 13767.46,1599.76 h60
  text "XX MIL VIAS REQUIRE NON-CONDUCTIVE FILL AND PLANARIZE" at 11576.38,1394.82 h59
  text "XX MIL VIAS REQUIRE CONDUCTIVE FILL AND PLANARIZE" at 11584.38,1290.84 h60
  text "OUTER XX MIL TRACES REQUIRE 50 OHM SINGLE-ENDED IMPEDANCE" at 11583.39,1127.46 h58
  text "LAYER 2 & 3 (INNER LAYERS) XX MIL WIDE, XX MIL SPACE / TRACES REQUIRE 100 OHM DIFFERENTIAL IMPEDANCE" at 11575.39,891.74 h60
  text ".Layer_Name" at 577,-858.49 h60
M11 Gerber Information:
  lines w10: -292,-930.17 6308,-930.17 ; -292,-726.83 6310,-726.83 ; -292,-523.5 -292,-1133.5 3713,-1133.5 6310,-1133.5 6310,-523.5 -291.5,-523.5 -291.5,-1133.5 1284,-1133.5 ; 2173,-1133.5 2173,-523.5 ; 3440,-726.83 3440,-523.5 ; 4280,-726.83 4280,-523.5 ; 4902,-1140 4902,-937.17
  text "ALL ARTWORK VIEWED FROM TOP SIDE" at -228.5,-655.67 h60
  text "BOARD #:" at 2248,-655.67 h60
  text ".PRJ_Number" at 2793.5,-655.67 h60
  text "REV:" at 3638,-655.67 h60
  text ".PCB_Rev" at 3929.5,-655.67 h60
  text "SVN REV:" at 4476,-655.67 h60
  text ".VersionControl_RevNumber" at 4982,-655.67 h60
  text "LAYER NAME =" at -228.5,-858.49 h60
  text "TID #:" at 2248,-859 h60
  text ".TID" at 2793.5,-859 h60
  text "PLOT NAME =" at -228.5,-1064.34 h60
  text ".plot_File_Name" at 577,-1064.34 h60
  text "GENERATED    :" at 2250,-1064.34 h60
  text ".Print_Date" at 3119.5,-1064.34 h60
  text ".Print_Time" at 3848.5,-1064.34 h60
  text "TEXAS INSTRUMENTS" at 5113,-1064.34 h60
M12 Stackup:
  drawing of 295 lines, arcs and shapes, not listed
  text "Layer" at 9821.59,7874.94 h60
  text "Name" at 10231.51,7874.94 h60
  text "Material" at 11161.25,7874.94 h60
  text "Thickness" at 12021.02,7874.94 h60
  text "Constant" at 12670.85,7874.94 h60
  text "Board Layer Stack" at 13240.71,7874.94 h60
  text "Top Overlay" at 10231.51,7754.94 h60
  text "Top Solder" at 10231.51,7634.94 h60
  text "Solder Resist" at 11161.25,7634.94 h60
  text "0.40mil" at 12021.02,7634.94 h60
  text "3.5" at 12670.85,7634.94 h60
  text "1" at 9821.59,7514.94 h60
  text "Top Layer 1" at 10231.51,7514.94 h60
  text "CF-004" at 11161.25,7514.94 h60
  text "2.76mil" at 12021.02,7514.94 h60
  text "Dielectric 1" at 10231.51,7394.94 h60
  text "PP-006" at 11161.25,7394.94 h60
  text "2.80mil" at 12021.02,7394.94 h60
  text "4.1" at 12670.85,7394.94 h60
  text "2" at 9821.59,7274.94 h60
  text "Layer 2" at 10231.51,7274.94 h60
  text "2.76mil" at 12021.02,7274.94 h60
  text "Dielectric1" at 10231.51,7154.94 h60
  text "FR-4 High Tg" at 11161.25,7154.94 h60
  text "59.20mil" at 12021.02,7154.94 h60
  text "4.8" at 12670.85,7154.94 h60
  text "3" at 9821.59,7034.94 h60
  text "Layer 3" at 10231.51,7034.94 h60
  text "2.76mil" at 12021.02,7034.94 h60
  text "Dielectric 2" at 10231.51,6914.94 h60
  text "PP-006" at 11161.25,6914.94 h60
  text "2.80mil" at 12021.02,6914.94 h60
  text "4.1" at 12670.85,6914.94 h60
  text "4" at 9821.59,6794.94 h60
  text "Bottom Layer" at 10231.51,6794.94 h60
  text "CF-004" at 11161.25,6794.94 h60
  text "2.76mil" at 12021.02,6794.94 h60
  text "Bottom Solder" at 10231.51,6674.94 h60
  text "Solder Resist" at 11161.25,6674.94 h60
  text "0.40mil" at 12021.02,6674.94 h60
  text "3.5" at 12670.85,6674.94 h60
  text "Bottom Overlay" at 10231.51,6554.94 h60
  text ".Layer_Name" at 577,-858.49 h60
M13 Component Bodies Top:
  text ".Layer_Name" at 577,-858.49 h60
M14 Component Bodies Bottom:
  text ".Layer_Name" at 577,-858.49 h60
M15 Courtyards Top:
  text ".Layer_Name" at 577,-858.49 h60
M16 Courtyards Bottom:
  text ".Layer_Name" at 577,-858.49 h60
Drill Drawing:
  circle w10: c5409.25,1146.33 r33.33
  lines w10: 5375.92,213 5375.92,229.67 5392.58,246.33 5375.92,263 5375.92,279.67 5392.58,279.67 5409.25,263 5425.92,279.67 5442.58,279.67 5442.58,263 5425.92,246.33 5442.58,229.67 5442.58,213 5425.92,213 5409.25,229.67 5392.58,213 5375.92,213 ; 5375.92,379.67 5392.58,379.67 5409.25,363 5425.92,379.67 5442.58,379.67 5425.92,396.33 5442.58,413 5425.92,413 5409.25,429.67 5392.58,413 5375.92,413 5392.58,396.33 5375.92,379.67 ; 5375.92,513 5409.25,529.67 5442.58,513 5425.92,546.33 5442.58,579.67 5409.25,563 5375.92,579.67 5392.58,546.33 5375.92,513 ; 5375.92,679.67 5392.58,679.67 5392.58,663 5425.92,663 5425.92,679.67 5442.58,679.67 5442.58,713 5425.92,713 5425.92,729.67 5392.58,729.67 5392.58,713 5375.92,713 5375.92,679.67 ; 5375.92,879.67 5442.58,879.67 5409.25,813 5375.92,879.67 ; 5375.92,963 5442.58,963 5442.58,1029.67 5375.92,1029.67 5375.92,963 ; 5375.92,1263 5442.58,1263 5442.58,1329.67 5375.92,1329.67 5375.92,1263 ; 5375.92,1446.33 5409.25,1413 5442.58,1446.33 5409.25,1479.67 5375.92,1446.33 ; 5389.25,1276.33 5429.25,1276.33 5429.25,1316.33 5389.25,1316.33 5389.25,1276.33
  lines w15: 5316.12,168 11090.55,168 ; 5316.12,1518 11090.55,1518 ; 5867,18 5867,1668 ; 6456.84,18 6456.84,1668 ; 7606.51,18 7606.51,1668 ; 8112.38,18 8112.38,1668 ; 8846.19,18 8846.19,1668 ; 10455.7,18 10455.7,1668 ; 5316.12,18 11090.55,18 11090.55,1668 5316.12,1668 5316.12,18
  text "Symbol" at 5406.12,1563 h72
  text "Count" at 5912,1563 h72
  text "Hole Size" at 6501.84,1563 h72
  text "Plated" at 7651.51,1563 h72
  text "Hole Type" at 8157.38,1563 h72
  text "Drill Layer Pair" at 8891.19,1563 h72
  text "Via/Pad" at 10500.7,1563 h72
  text "48" at 5912,1413 h60
  text "7.87mil (0.200mm)" at 6501.84,1413 h60
  text "PTH" at 7651.51,1413 h60
  text "Round" at 8157.38,1413 h60
  text "Top Layer 1 - Bottom Layer" at 8891.19,1413 h60
  text "Via" at 10500.7,1413 h60
  text "11" at 5912,1263 h60
  text "10.00mil (0.254mm)" at 6501.84,1263 h60
  text "PTH" at 7651.51,1263 h60
  text "Round" at 8157.38,1263 h60
  text "Top Layer 1 - Bottom Layer" at 8891.19,1263 h60
  text "Via" at 10500.7,1263 h60
  text "89" at 5912,1113 h60
  text "16.00mil (0.406mm)" at 6501.84,1113 h60
  text "PTH" at 7651.51,1113 h60
  text "Round" at 8157.38,1113 h60
  text "Top Layer 1 - Bottom Layer" at 8891.19,1113 h60
  text "Via" at 10500.7,1113 h60
  text "3" at 5912,963 h60
  text "31.50mil (0.800mm)" at 6501.84,963 h60
  text "PTH" at 7651.51,963 h60
  text "Round" at 8157.38,963 h60
  text "Top Layer 1 - Bottom Layer" at 8891.19,963 h60
  text "Pad" at 10500.7,963 h60
  text "11" at 5912,813 h60
  text "40.00mil (1.016mm)" at 6501.84,813 h60
  text "PTH" at 7651.51,813 h60
  text "Round" at 8157.38,813 h60
  text "Top Layer 1 - Bottom Layer" at 8891.19,813 h60
  text "Pad" at 10500.7,813 h60
  text "6" at 5912,663 h60
  text "45.28mil (1.150mm)" at 6501.84,663 h60
  text "PTH" at 7651.51,663 h60
  text "Round" at 8157.38,663 h60
  text "Top Layer 1 - Bottom Layer" at 8891.19,663 h60
  text "Pad" at 10500.7,663 h60
  text "4" at 5912,513 h60
  text "49.21mil (1.250mm)" at 6501.84,513 h60
  text "PTH" at 7651.51,513 h60
  text "Round" at 8157.38,513 h60
  text "Top Layer 1 - Bottom Layer" at 8891.19,513 h60
  text "Pad" at 10500.7,513 h60
  text "3" at 5912,363 h60
  text "51.18mil (1.300mm)" at 6501.84,363 h60
  text "PTH" at 7651.51,363 h60
  text "Round" at 8157.38,363 h60
  text "Top Layer 1 - Bottom Layer" at 8891.19,363 h60
  text "Pad" at 10500.7,363 h60
  text "1" at 5912,213 h60
  text "104.33mil (2.650mm)" at 6501.84,213 h60
  text "PTH" at 7651.51,213 h60
  text "Round" at 8157.38,213 h60
  text "Top Layer 1 - Bottom Layer" at 8891.19,213 h60
  text "Pad" at 10500.7,213 h60
  text "176 Total" at 5912,63 h60
  text ".Layer_Name" at 577,-858.49 h60
M17 Embedded Cavity:
  text ".Layer_Name" at 577,-858.49 h60
M18 Embedded Assembly:
  text ".Layer_Name" at 577,-858.49 h60
M19 Embedded Keepout:
  text ".Layer_Name" at 577,-858.49 h60

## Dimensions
0,-400 to 1000,-400 on M2 Board Dimensions
0,0 to 0,3450 on M2 Board Dimensions
0,0 to 4950,0 on M2 Board Dimensions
